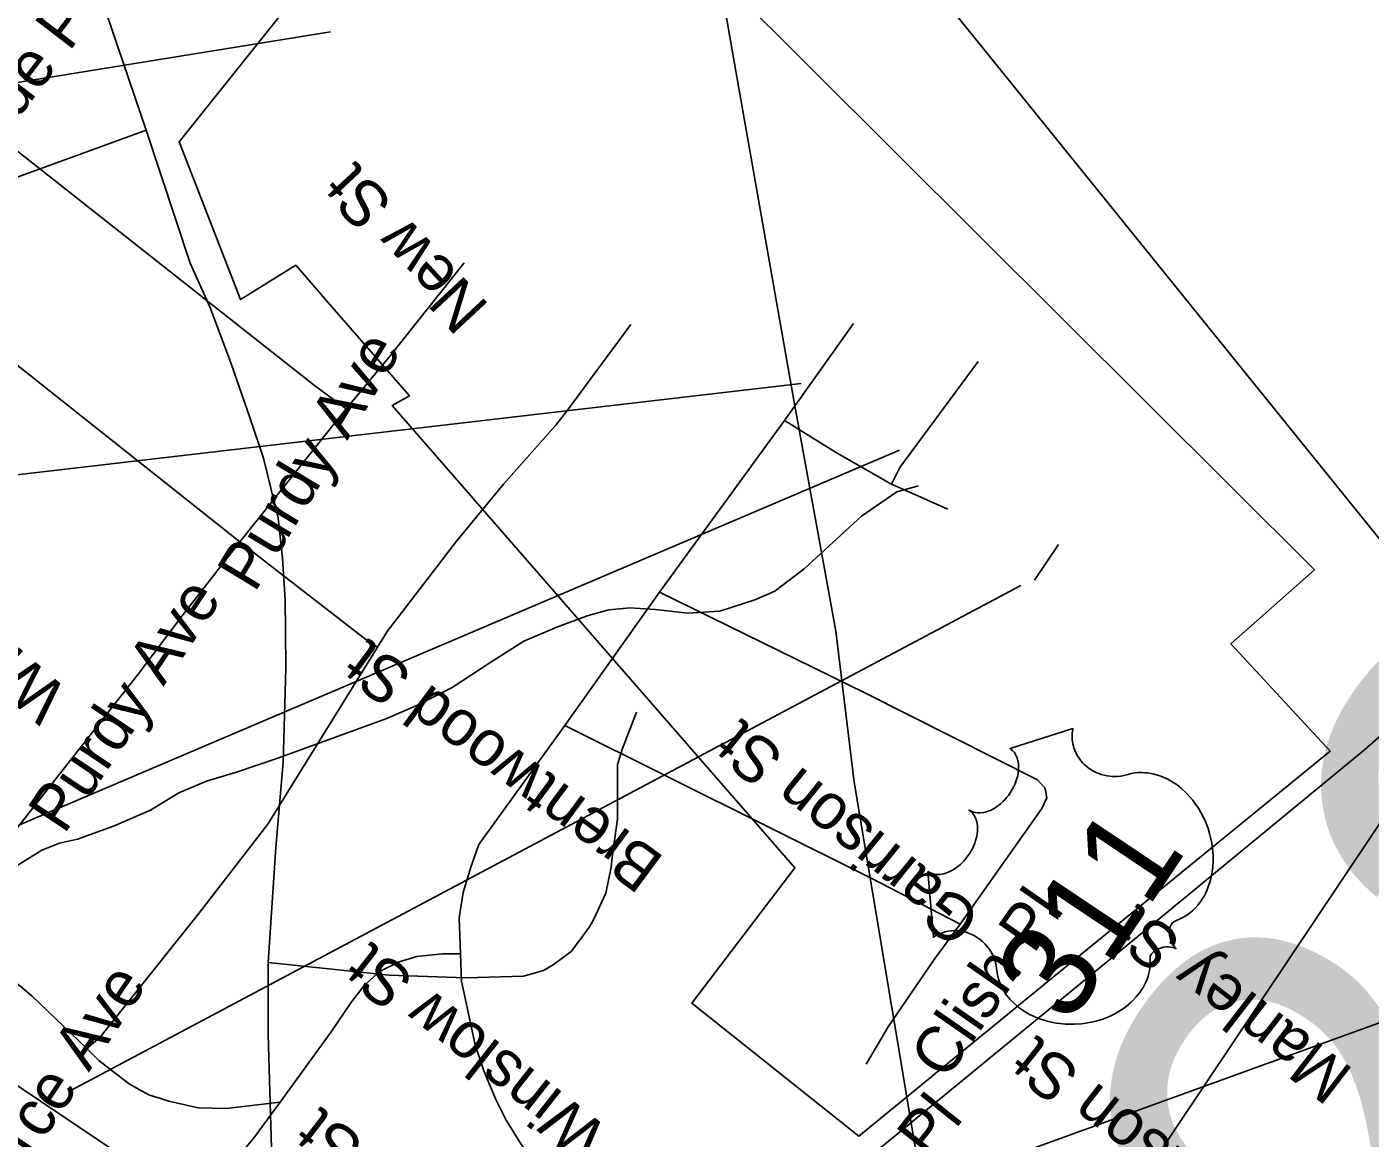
# Model space of a CAD drawing. Extents: x 1716282 to 1717158, y 799307 to 801078.
# Drawn here: x 1716855.69 to 1716895.75, y 800783.79 to 800816.94 of the extents above; entities that cross this region are included whole.
import ezdxf

# ---------------------------------------------------------------- set-up
doc = ezdxf.new("R2010")
doc.units = 0
for name, color, linetype in [('Exist Boundary Political City Limit New', 7, 'Continuous'), ('Exist Hydrographic Misc Water Feature', 7, 'Continuous'), ('Exist Road Non-System Structure Non-Sys Other Number Label', 7, 'Continuous'), ('Exist Road Non-System Type 51', 7, 'Continuous'), ('Exist Road Non-System Type 51 Label', 7, 'Continuous'), ('Exist Road Primary Interstate Structure Cantilever Sign Number Label', 7, 'Continuous'), ('Exist Road Primary NC Attributed', 7, 'Continuous'), ('Exist Road Primary US Shield CELL', 7, 'Continuous'), ('Exist Road Primary US Shield Number Label', 7, 'Continuous'), ('Exist Road Primary US Structure Ovrhead Sign CELL', 7, 'Continuous'), ('Exist Road Primary US Structure Standard Bridge Number Label', 7, 'Continuous'), ('Exist Road Secondary Structure Standard Bridge Number Label', 7, 'Continuous'), ('Exist Road Secondary Type 51 Attributed', 7, 'Continuous'), ('Exist Utilities Electrical Transmission Line', 7, 'Continuous'), ('Map Preparation Boundary City Limit Buffer Line', 7, 'Continuous'), ('Prop DSN Text', 7, 'Continuous')]:
    doc.layers.add(name, color=color, linetype=linetype)

msp = doc.modelspace()

# ---------------------------------------------------------------- linework, layer by layer
at = {"layer": 'Exist Boundary Political City Limit New'}
msp.add_lwpolyline([(1716871.549, 800823.205), (1716894.085, 800800.74), (1716891.595, 800798.533), (1716894.559, 800795.329), (1716886.245, 800788.544), (1716880.504, 800783.841), (1716875.518, 800787.81), (1716878.595, 800791.848), (1716866.586, 800805.641), (1716867.094, 800805.929), (1716864.784, 800808.588), (1716863.706, 800809.829), (1716862.054, 800808.811), (1716860.228, 800813.508), (1716869.56, 800825.197), (1716871.549, 800823.205)], dxfattribs=at)
at = {"layer": 'Exist Hydrographic Misc Water Feature'}
msp.add_lwpolyline([(1716882.283, 800803.251), (1716881.629, 800803.064), (1716880.576, 800802.346), (1716879.722, 800801.558), (1716878.868, 800800.771), (1716877.992, 800800.105), (1716877.394, 800799.847), (1716876.352, 800799.504), (1716875.402, 800799.451), (1716874.421, 800799.56), (1716873.682, 800799.607), (1716873.045, 800799.549), (1716872.393, 800799.365), (1716871.494, 800799.029), (1716870.509, 800798.613), (1716869.52, 800797.989), (1716868.369, 800797.23), (1716867.34, 800796.702), (1716866.395, 800796.295), (1716863.172, 800795.123), (1716861.936, 800794.703), (1716861.048, 800794.432), (1716860.215, 800794.086), (1716859.372, 800793.573), (1716858.273, 800793.094), (1716857.198, 800792.705), (1716856.659, 800792.583), (1716856.133, 800792.378), (1716853.443, 800790.705)], dxfattribs=at)
at = {"layer": 'Exist Road Non-System Type 51'}
for p, q in [((1716878.286, 800805.195), (1716880.343, 800808.095)), ((1716862.036, 800801.577), (1716865.214, 800805.545)), ((1716874.55, 800800.071), (1716878.286, 800805.195)), ((1716881.469, 800803.298), (1716883.15, 800802.553)), ((1716871.728, 800796.101), (1716874.55, 800800.071)), ((1716863.552, 800794.244), (1716866.145, 800798.431)), ((1716853.184, 800790.227), (1716859.006, 800797.633))]:
    msp.add_line(p, q, dxfattribs=at)
for points in [[(1716851.061, 800816.654), (1716864.269, 800806.241), (1716865.214, 800805.545)], [(1716847.932, 800812.711), (1716848.445, 800812.239), (1716854.224, 800807.771), (1716862.036, 800801.577)], [(1716865.214, 800805.545), (1716866.522, 800807.124), (1716868.726, 800809.904)], [(1716866.145, 800798.431), (1716866.434, 800798.899), (1716868.497, 800801.599), (1716869.899, 800803.302), (1716871.46, 800805.06), (1716871.778, 800805.466), (1716873.702, 800808.06)], [(1716881.469, 800803.298), (1716881.724, 800803.79), (1716884.056, 800806.96)], [(1716878.286, 800805.195), (1716879.858, 800804.223), (1716881.469, 800803.298)], [(1716859.006, 800797.633), (1716860.344, 800799.413), (1716862.036, 800801.577)], [(1716862.036, 800801.577), (1716865.793, 800798.667), (1716866.145, 800798.431)], [(1716883.519, 800790.174), (1716885.958, 800793.619), (1716886.11, 800793.941), (1716886.074, 800794.107), (1716886.048, 800794.233), (1716885.829, 800794.472), (1716880.675, 800797.075), (1716874.55, 800800.071)], [(1716868.924, 800791.869), (1716869.167, 800792.548), (1716871.728, 800796.101)], [(1716871.728, 800796.101), (1716880.844, 800791.553), (1716883.519, 800790.174)], [(1716857.479, 800786.465), (1716857.864, 800786.792), (1716860.805, 800790.481), (1716862.87, 800793.156), (1716863.552, 800794.244)], [(1716868.622, 800789.284), (1716868.581, 800790.358), (1716868.7, 800791.116), (1716868.924, 800791.869)], [(1716853.184, 800790.227), (1716855.843, 800788.022), (1716857.479, 800786.465)], [(1716880.723, 800785.988), (1716881.375, 800787.108), (1716882.751, 800789.114), (1716883.519, 800790.174)], [(1716863.245, 800784.863), (1716864.767, 800786.959), (1716865.344, 800787.822), (1716865.745, 800788.337), (1716866.224, 800788.767), (1716866.792, 800789.047), (1716867.314, 800789.206), (1716868.08, 800789.289), (1716868.622, 800789.284)], [(1716873.268, 800780.604), (1716871.626, 800782.148), (1716871.068, 800782.779), (1716870.435, 800783.591), (1716869.985, 800784.322), (1716869.676, 800784.941), (1716869.32, 800785.79), (1716869.061, 800786.567), (1716868.648, 800788.468), (1716868.622, 800789.284)], [(1716857.479, 800786.465), (1716857.83, 800786.106), (1716858.747, 800785.401), (1716859.325, 800785.081), (1716859.92, 800784.891), (1716860.8, 800784.687), (1716861.635, 800784.667), (1716863.245, 800784.863)], [(1716842.177, 800775.411), (1716842.533, 800775.21), (1716842.752, 800775.21), (1716843.723, 800775.6), (1716844.159, 800775.703), (1716844.543, 800775.743), (1716848.824, 800775.818), (1716850.05, 800775.959), (1716851.719, 800776.353), (1716853.383, 800776.943), (1716854.509, 800777.498), (1716855.466, 800778.077), (1716856.334, 800778.695), (1716858.161, 800780.1), (1716860.29, 800781.57), (1716860.959, 800782.125), (1716861.565, 800782.714), (1716862.464, 800783.805), (1716863.245, 800784.863)]]:
    msp.add_lwpolyline(points, dxfattribs=at)
at = {"layer": 'Exist Road Primary Interstate Structure Cantilever Sign Number Label'}
msp.add_line((1716881.717, 800804.31), (1716849.394, 800790.547), dxfattribs=at)
at = {"layer": 'Exist Road Primary NC Attributed'}
msp.add_lwpolyline([(1716867.599, 800772.349), (1716871.334, 800775.429), (1716874.74, 800778.239), (1716879.543, 800782.182), (1716888.216, 800789.306), (1716895.583, 800795.371), (1716897.845, 800797.368), (1716900.138, 800799.371), (1716900.27, 800799.505)], dxfattribs=at)
at = {"layer": 'Exist Road Primary US Shield CELL'}
msp.add_lwpolyline([(1716882.559, 800791.742), (1716882.614, 800791.709), (1716882.686, 800791.68), (1716882.725, 800791.668), (1716882.807, 800791.656), (1716882.912, 800791.656), (1716883.03, 800791.675), (1716883.144, 800791.709), (1716883.211, 800791.739), (1716883.317, 800791.795), (1716883.425, 800791.866), (1716883.53, 800791.955), (1716883.628, 800792.052), (1716883.725, 800792.167), (1716883.808, 800792.287), (1716883.887, 800792.425), (1716883.956, 800792.589), (1716883.983, 800792.668), (1716884.008, 800792.76), (1716884.026, 800792.849), (1716884.036, 800792.953), (1716884.038, 800793.04), (1716884.035, 800793.112), (1716884.015, 800793.223), (1716883.984, 800793.322), (1716883.962, 800793.37), (1716883.938, 800793.414), (1716883.879, 800793.493), (1716883.85, 800793.523), (1716883.783, 800793.576), (1716883.845, 800793.541), (1716883.887, 800793.522), (1716883.929, 800793.507), (1716883.978, 800793.497), (1716884.051, 800793.487), (1716884.117, 800793.487), (1716884.222, 800793.499), (1716884.279, 800793.513), (1716884.327, 800793.527), (1716884.445, 800793.574), (1716884.565, 800793.642), (1716884.62, 800793.677), (1716884.673, 800793.716), (1716884.736, 800793.768), (1716884.797, 800793.825), (1716884.853, 800793.884), (1716884.908, 800793.945), (1716884.96, 800794.011), (1716885, 800794.067), (1716885.046, 800794.137), (1716885.085, 800794.204), (1716885.121, 800794.275), (1716885.158, 800794.355), (1716885.184, 800794.422), (1716885.215, 800794.513), (1716885.237, 800794.599), (1716885.251, 800794.678), (1716885.263, 800794.786), (1716885.266, 800794.877), (1716885.259, 800794.949), (1716885.245, 800795.039), (1716885.219, 800795.133), (1716885.195, 800795.194), (1716885.164, 800795.247), (1716885.129, 800795.3), (1716885.086, 800795.347), (1716885.046, 800795.383), (1716885.008, 800795.41), (1716886.886, 800796.007), (1716886.877, 800795.969), (1716886.864, 800795.877), (1716886.86, 800795.8), (1716886.863, 800795.67), (1716886.872, 800795.61), (1716886.882, 800795.548), (1716886.897, 800795.488), (1716886.912, 800795.434), (1716886.938, 800795.362), (1716886.968, 800795.294), (1716887.003, 800795.224), (1716887.036, 800795.167), (1716887.112, 800795.059), (1716887.165, 800794.996), (1716887.212, 800794.947), (1716887.316, 800794.856), (1716887.368, 800794.816), (1716887.422, 800794.78), (1716887.481, 800794.745), (1716887.539, 800794.713), (1716887.602, 800794.685), (1716887.658, 800794.661), (1716887.73, 800794.636), (1716887.816, 800794.611), (1716887.904, 800794.593), (1716888.054, 800794.577), (1716888.218, 800794.576), (1716888.318, 800794.587), (1716888.407, 800794.604), (1716888.527, 800794.638), (1716888.593, 800794.656), (1716888.676, 800794.672), (1716888.822, 800794.69), (1716888.888, 800794.693), (1716888.959, 800794.693), (1716889.03, 800794.689), (1716889.105, 800794.683), (1716889.169, 800794.675), (1716889.309, 800794.647), (1716889.437, 800794.608), (1716889.503, 800794.586), (1716889.645, 800794.526), (1716889.713, 800794.493), (1716889.842, 800794.421), (1716889.991, 800794.322), (1716890.124, 800794.217), (1716890.27, 800794.08), (1716890.354, 800793.993), (1716890.446, 800793.882), (1716890.523, 800793.784), (1716890.63, 800793.627), (1716890.701, 800793.504), (1716890.78, 800793.354), (1716890.824, 800793.258), (1716890.869, 800793.15), (1716890.916, 800793.021), (1716890.962, 800792.877), (1716891.002, 800792.713), (1716891.027, 800792.585), (1716891.05, 800792.426), (1716891.059, 800792.332), (1716891.067, 800792.202), (1716891.066, 800792.031), (1716891.056, 800791.87), (1716891.04, 800791.737), (1716891.019, 800791.624), (1716890.986, 800791.481), (1716890.912, 800791.257), (1716890.88, 800791.179), (1716890.838, 800791.089), (1716890.794, 800791.008), (1716890.749, 800790.931), (1716890.682, 800790.831), (1716890.609, 800790.737), (1716890.532, 800790.652), (1716890.446, 800790.568), (1716890.348, 800790.486), (1716890.249, 800790.418), (1716890.141, 800790.355), (1716889.935, 800790.263), (1716889.88, 800790.234), (1716889.856, 800790.213), (1716889.812, 800790.154), (1716889.785, 800790.088), (1716889.769, 800790.013), (1716889.764, 800789.965), (1716889.764, 800789.897), (1716889.768, 800789.841), (1716889.781, 800789.77), (1716889.795, 800789.716), (1716889.807, 800789.675), (1716889.847, 800789.583), (1716889.87, 800789.545), (1716889.902, 800789.499), (1716889.956, 800789.442), (1716889.862, 800789.476), (1716889.793, 800789.488), (1716889.73, 800789.491), (1716889.671, 800789.489), (1716889.589, 800789.479), (1716889.524, 800789.465), (1716889.452, 800789.443), (1716889.387, 800789.412), (1716889.338, 800789.385), (1716889.298, 800789.357), (1716889.256, 800789.318), (1716889.228, 800789.283), (1716889.208, 800789.251), (1716889.189, 800789.202), (1716889.192, 800789.116), (1716889.193, 800789.036), (1716889.19, 800788.951), (1716889.18, 800788.855), (1716889.17, 800788.787), (1716889.152, 800788.708), (1716889.128, 800788.62), (1716889.096, 800788.527), (1716889.058, 800788.436), (1716889.021, 800788.357), (1716888.977, 800788.276), (1716888.933, 800788.206), (1716888.884, 800788.134), (1716888.834, 800788.071), (1716888.775, 800787.997), (1716888.696, 800787.91), (1716888.624, 800787.842), (1716888.545, 800787.773), (1716888.459, 800787.704), (1716888.361, 800787.635), (1716888.233, 800787.552), (1716888.137, 800787.499), (1716887.978, 800787.42), (1716887.774, 800787.34), (1716887.607, 800787.288), (1716887.476, 800787.255), (1716887.271, 800787.217), (1716887.142, 800787.199), (1716886.922, 800787.184), (1716886.768, 800787.183), (1716886.66, 800787.188), (1716886.49, 800787.203), (1716886.387, 800787.218), (1716886.241, 800787.245), (1716886.112, 800787.277), (1716885.993, 800787.311), (1716885.918, 800787.336), (1716885.792, 800787.385), (1716885.705, 800787.422), (1716885.588, 800787.479), (1716885.47, 800787.547), (1716885.366, 800787.615), (1716885.281, 800787.675), (1716885.187, 800787.752), (1716885.092, 800787.841), (1716885.014, 800787.923), (1716884.96, 800787.985), (1716884.898, 800788.066), (1716884.834, 800788.161), (1716884.777, 800788.26), (1716884.734, 800788.348), (1716884.692, 800788.449), (1716884.662, 800788.542), (1716884.634, 800788.655), (1716884.615, 800788.767), (1716884.606, 800788.863), (1716884.583, 800788.986), (1716884.565, 800789.054), (1716884.534, 800789.141), (1716884.503, 800789.216), (1716884.472, 800789.28), (1716884.423, 800789.369), (1716884.382, 800789.43), (1716884.316, 800789.517), (1716884.265, 800789.572), (1716884.197, 800789.64), (1716884.131, 800789.699), (1716884.042, 800789.764), (1716883.964, 800789.812), (1716883.869, 800789.862), (1716883.773, 800789.902), (1716883.686, 800789.931), (1716883.58, 800789.956), (1716883.498, 800789.969), (1716883.381, 800789.976), (1716883.267, 800789.973), (1716883.166, 800789.96), (1716883.071, 800789.941), (1716882.992, 800789.915), (1716882.92, 800789.888), (1716882.837, 800789.849), (1716882.764, 800789.807), (1716882.722, 800789.778)], close=True, dxfattribs=at)
at = {"layer": 'Exist Road Primary US Structure Ovrhead Sign CELL'}
for p, q in [((1716864.747, 800816.791), (1716830.126, 800811.192)), ((1716885.743, 800800.434), (1716886.457, 800801.501)), ((1716885.332, 800800.278), (1716856.982, 800785.195))]:
    msp.add_line(p, q, dxfattribs=at)
msp.add_lwpolyline([(1716841.091, 800767.359), (1716853.834, 800786.398), (1716858.342, 800783.38), (1716845.599, 800764.341)], close=True, dxfattribs=at)
at = {"layer": 'Exist Road Primary US Structure Standard Bridge Number Label'}
for p, q in [((1716896.1, 800801.58), (1716868.305, 800835.983)), ((1716898.368, 800788.083), (1716859.92, 800774.132))]:
    msp.add_line(p, q, dxfattribs=at)
at = {"layer": 'Exist Road Secondary Structure Standard Bridge Number Label'}
msp.add_line((1716878.783, 800806.299), (1716828.871, 800800.492), dxfattribs=at)
at = {"layer": 'Exist Road Secondary Type 51 Attributed'}
for points in [[(1716866.929, 800856.114), (1716859.517, 800846.414), (1716857.495, 800843.059), (1716856.168, 800840.069), (1716855.423, 800836.689), (1716855.159, 800833.411), (1716855.622, 800829.765), (1716856.274, 800825.451), (1716857.521, 800818.927), (1716859.245, 800813.862)], [(1716859.245, 800813.862), (1716854.568, 800812.162), (1716852.423, 800811.055), (1716849.219, 800808.564)], [(1716859.245, 800813.862), (1716860.555, 800809.891), (1716861.139, 800808.59), (1716861.765, 800806.945), (1716862.339, 800805.289), (1716862.749, 800804.069), (1716863.177, 800802.285), (1716863.311, 800801.093), (1716863.392, 800799.84), (1716863.405, 800798.936), (1716863.408, 800797.795), (1716863.335, 800794.999), (1716863.115, 800792.459), (1716862.884, 800789.028)], [(1716862.884, 800789.028), (1716866.488, 800788.649), (1716868.783, 800788.573), (1716870.498, 800788.621), (1716871.09, 800788.785), (1716871.386, 800788.955), (1716871.917, 800789.352), (1716872.164, 800789.683), (1716872.462, 800790.086), (1716872.597, 800790.32), (1716872.95, 800791.094), (1716873.115, 800791.869), (1716873.145, 800792.163), (1716873.304, 800793.312), (1716873.303, 800794.929), (1716873.447, 800795.408), (1716873.867, 800796.499)], [(1716862.884, 800789.028), (1716862.882, 800786.871), (1716862.99, 800783.159), (1716863.243, 800781.618), (1716864.034, 800778.831), (1716865.143, 800776.452), (1716867.599, 800772.349)]]:
    msp.add_lwpolyline(points, dxfattribs=at)
at = {"layer": 'Exist Utilities Electrical Transmission Line'}
msp.add_lwpolyline([(1716891.042, 800732.059), (1716889.678, 800739.724), (1716887.751, 800750.356), (1716886.331, 800759.011), (1716885.425, 800764.285), (1716883.133, 800777.808), (1716880.36, 800794.405), (1716879.81, 800798.907), (1716878.572, 800805.747), (1716876.827, 800815.618), (1716875.736, 800821.896), (1716874.127, 800831.603), (1716872.289, 800842.52), (1716871.049, 800850.314), (1716869.866, 800856.867), (1716868.611, 800863.725)], dxfattribs=at)
at = {"layer": 'Map Preparation Boundary City Limit Buffer Line'}
msp.add_lwpolyline([(1716871.549, 800823.205), (1716894.085, 800800.74), (1716891.595, 800798.533), (1716894.559, 800795.329), (1716886.245, 800788.544), (1716880.504, 800783.841), (1716875.518, 800787.81), (1716878.595, 800791.848), (1716866.586, 800805.641), (1716867.094, 800805.929), (1716864.784, 800808.588), (1716863.706, 800809.829), (1716862.054, 800808.811), (1716860.228, 800813.508), (1716869.56, 800825.197), (1716871.549, 800823.205)], dxfattribs=at)
at = {"layer": 'Prop DSN Text'}
for points in [[(1716644.267, 800417.02), (1716922.463, 800832.664), (1716560.178, 801075.146), (1716281.982, 800659.503)], [(1716644.267, 800417.02), (1716922.463, 800832.664), (1716967.08, 800802.801), (1716688.884, 800387.158)]]:
    msp.add_lwpolyline(points, close=True, dxfattribs=at)

# ---------------------------------------------------------------- texts
at = {"layer": 'Exist Road Non-System Structure Non-Sys Other Number Label'}
msp.add_text('J422', height=15.223, rotation=56.2051, dxfattribs=at).set_placement((1716886.6, 800756.411))
at = {"layer": 'Exist Road Non-System Type 51 Label'}
for s, rotation, p in [('Wade Pl', 52.5599, (1716853.708, 800811.953)), ('New St', 132.9251, (1716869.514, 800808.613)), ('Purdy Ave', 58.7657, (1716862.479, 800800.032)), ('Winslow St', 139.0636, (1716856.977, 800797.102)), ('Purdy Ave', 56.2051, (1716856.797, 800792.822)), ('Brentwood St', 143.5228, (1716874.745, 800792.138)), ('Garrison St', 141.0137, (1716884.22, 800790.474)), ('Clish Pl', 55.1872, (1716883.083, 800785.472)), ('Manley St', 142.4477, (1716895.292, 800785.809)), ('Winslow St', 141.7726, (1716873.087, 800784.034)), ('E Commerce Ave', 56.2051, (1716851.269, 800776.381)), ('Garrison St', 141.9054, (1716893.121, 800781.129)), ('Wingate Pl', 51.4506, (1716878.094, 800777.404)), ('Worth St', 142.4718, (1716870.108, 800780.38))]:
    msp.add_text(s, height=1.3775, rotation=rotation, dxfattribs=at).set_placement(p)
at = {"layer": 'Exist Road Primary US Shield Number Label'}
msp.add_text('311', height=2.8275, rotation=56.2051, dxfattribs=at).set_placement((1716886.767, 800787.112))

doc.saveas('drawing.dxf')
